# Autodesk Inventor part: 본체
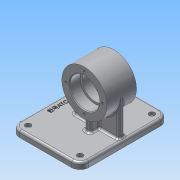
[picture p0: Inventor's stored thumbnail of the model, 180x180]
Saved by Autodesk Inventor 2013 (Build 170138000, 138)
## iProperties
Created: 2019-09
Part Number: 본체
Material: 알루미늄 6061
Document SubType Name: Modeling
Designer: Administrator
Density: 2.71 g/cm^3
Mass: 556.668 g
Surface Area: 495.884 cm^2
Volume: 205.413 cm^3
Author: Administrator
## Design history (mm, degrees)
sketch "스케치1"
  geometry: L1 (-62, -59)-(36, -59); L2 (36, -59)-(36, -50); L3 (36, -50)-(-62, -50); L4 (-62, -50)-(-62, -59); L5 (-62, -59)-(36, -50); L6 (36, -59)-(-62, -50); C1 r 32 at (0, 0); 2 further points
  constraints: 12 end point, 2 midpoint, 2 parallel, 1 centre point, 1 coincident, 1 horizontal, 1 perpendicular
  dimensions: "d0" = 64 diameter of C1; "d1" = 98 distance of L3.end L2.end; "d2" = 9 distance of L2.end L1.end; "d3" = 59 distance from line of C1.centre L1; "d4" = 36 distance from line of point (0, 0) L2
extrude "돌출1" new body sketch "스케치1" distance "d5" = 21; taper "d6" = 0 deg
sketch "스케치2"
  geometry: C1 r 32 at (0, 0) reference
hole "구멍1" sketch "스케치2" at (0, 0) diameter "d9" = 36; stored, may be unused: countersink angle "d13" = 90 deg, drill point angle "d15" = 118 deg; dims "d10" = 6, "d11" = 42, "d12" = 15, "d14" = 8
sketch "스케치3"
  geometry: C1 r 21 at (0, 0) reference; 1 further point
  constraints: 1 vertical alignment
  dimensions: "d16" = 26 distance of C1.centre point (0, 26)
hole "구멍2" sketch "스케치3" at (0, 26) diameter "d17" = 3.242; stored, may be unused: countersink angle "d21" = 90 deg, drill point angle "d23" = 118 deg; dims "d18" = 8, "d19" = 42, "d20" = 15, "d22" = 10
chamfer "모따기1" distance "d27" = 1; stored, may be unused: second distance "d28" = 2, angle "d29" = 45 deg
fillet "모깎기1" dims "d30" = 0.3
extrude "돌출3" join sketch "스케치1" stored distance "d31" = 126; taper "d32" = 0 deg
sketch "스케치4"
  geometry: L1 (66, 46)-(58, 46); L2 (58, 46)-(58, 80); L3 (58, 80)-(66, 80); L4 (66, 80)-(66, 46); L5 (66, 46)-(58, 80); L6 (58, 46)-(66, 80); L7 (30, 59)-(94, 59); L8 (94, 59)-(94, 67); L9 (94, 67)-(30, 67); L10 (30, 67)-(30, 59); L11 (30, 59)-(94, 67); L12 (94, 59)-(30, 67); 5 further points
  constraints: 24 end point, 7 midpoint, 4 parallel, 2 horizontal, 2 perpendicular, 1 coincident
  dimensions: "d33" = 8 distance of L2.end L3.end; "d34" = 34 distance of L1.end L2.end; "d35" = 64 distance of L9.end L8.end; "d36" = 8 distance of L8.end L7.end
extrude "돌출4" join sketch "스케치4" stored distance "d37" = 126; taper "d38" = 0 deg
extrude "돌출5" join sketch "스케치4" stored distance "d39" = 126; taper "d40" = 0 deg
sketch "스케치5"
  geometry: C1 r 18 at (0, 0) reference; C2 r 18 at (0, 0)
  constraints: 1 centre point, 1 coincident
  dimensions: "d41" = 36 diameter of C2
extrude "돌출6" cut sketch "스케치5" distance "d42" = 126; taper "d43" = 0 deg
sketch "스케치6"
  geometry: 1 further point
fillet "모깎기2" dims "d44" = 12
sketch "스케치7"
  geometry: A1 r 12 centre (74, 12) between (74, 0) and (86, 12) reference; 1 further point
hole "구멍3" sketch "스케치7" at (74, 12) diameter "d45" = 4.5; stored, may be unused: countersink angle "d49" = 90 deg, drill point angle "d51" = 118 deg; dims "d46" = 8, "d47" = 8, "d48" = 4.4, "d50" = 10
node "작업 평면1"
fillet "모깎기3" dims "d52" = 3
fillet "모깎기4" dims "d53" = 3
fillet "모깎기5" dims "d54" = 3
sketch "스케치8"
  geometry: L1 (74, 3)-(0, 3) reference; L2 (-12, -111)-(-12, -9) reference; 2 further points
  constraints: 1 other
  dimensions: "d55" = 63 distance from line of L1 point (-2, -60); "d56" = 10 distance from line of L2 point (-2, -60)
feature "엠보싱1" sketch "스케치8" dims "d57" = 0.5, "d58" = 0
fillet "모깎기6" dims "d59" = 3
fillet "모깎기7" dims "d60" = 3
node "솔리드1"
pattern_circular "원형 패턴1" dims angle "d25" = 360 deg
mirror "대칭1"
mirror "대칭2"
mirror "대칭3"
